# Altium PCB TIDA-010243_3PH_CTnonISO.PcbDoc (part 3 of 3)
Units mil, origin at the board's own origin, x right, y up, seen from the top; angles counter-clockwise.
Board outline 6131.89 x 7490.17 mil, 2 copper layers (Top Layer, Bottom Layer), stack 62 mil thick; 208 components, 218 nets, 747 pads, 147 vias.
Unrouted connection lines stored in the file: 258.
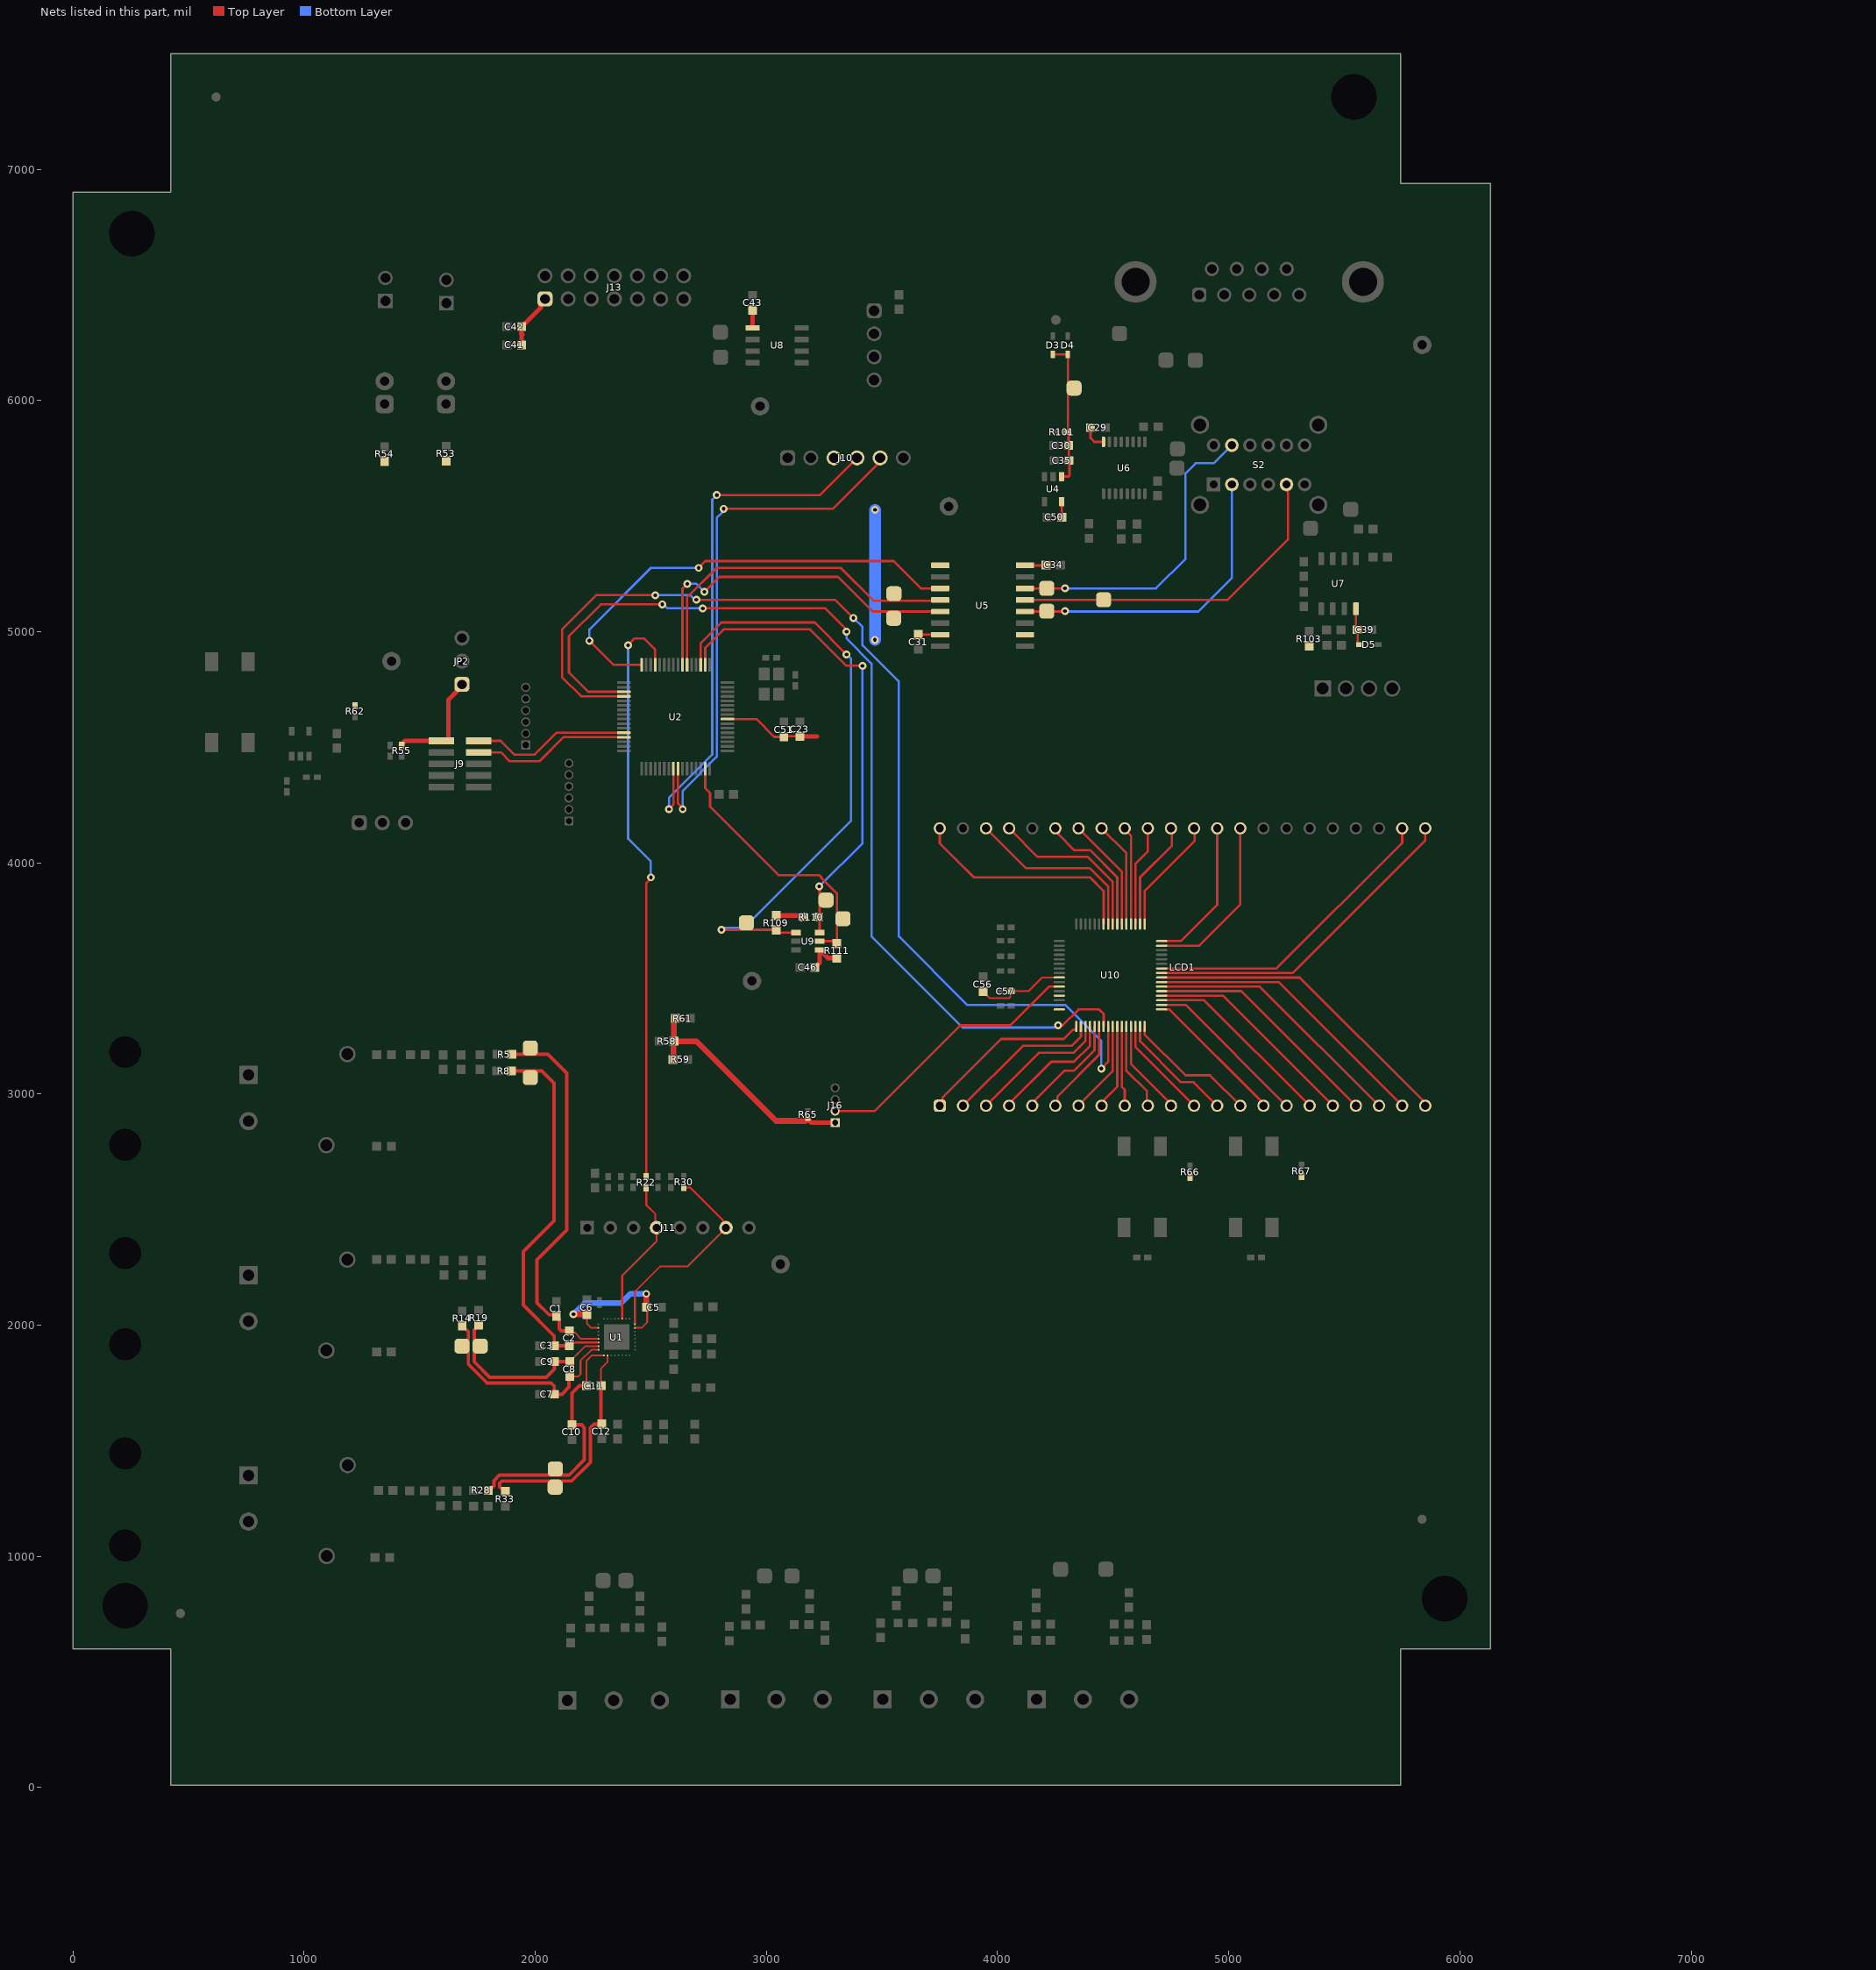
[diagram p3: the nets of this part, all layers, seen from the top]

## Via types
v1: diameter 34, hole 16, Top Layer to Bottom Layer, 97 vias
v2: diameter 34, hole 16, Top Layer to Bottom Layer, tented both sides, 41 vias
v3: diameter 23.62, hole 11.81, Top Layer to Bottom Layer, 9 vias

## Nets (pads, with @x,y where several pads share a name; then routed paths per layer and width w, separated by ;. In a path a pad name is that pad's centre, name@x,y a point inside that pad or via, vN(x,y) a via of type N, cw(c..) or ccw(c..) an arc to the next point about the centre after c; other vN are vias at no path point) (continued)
RXD_FTDI: J10.5 U2.25 | length 2333.1
  Top Layer w10: U2.25@2617.23,4407.26 2617.23,4256.97 2637.8,4236.4 v1(2637.8,4232.28) ; v2(2814.96,5531.5) 3287.4,5531.5 3476.02,5720.12 3476.02,5720.68 3491.88,5736.54 J10.5@3491.88,5751.41
  Bottom Layer w10: v1(2637.8,4232.28) 2637.8,4311.02 2785.43,4458.66 2785.43,5492.13 2807.25,5513.95 2807.25,5517.3 2814.96,5525 v2(2814.96,5531.5)
S0: LCD1.34 U10.50 | length 445.9
  Top Layer w10: U10.50@4616.14,3735.24 4616.14,3937.01 4753.94,4074.8 LCD1.34@4753.94,4124.02
S1: LCD1.33 U10.49 | length 502.2
  Top Layer w10: U10.49@4635.83,3735.24 4635.83,3877.95 4852.85,4094.97 4852.85,4134.34 LCD1.33@4862.2,4143.7
S2: LCD1.32 U10.48 | length 640.7
  Top Layer w10: U10.48@4709.65,3661.42 4793.31,3661.42 4950,3818.11 LCD1.32@4950,4149.21 ; LCD1.32@4950.79,4149.21 LCD1.32@4950.79,4153.54
S3: LCD1.31 U10.47 | length 743.6
  Top Layer w10: U10.47@4709.65,3641.73 4872.05,3641.73 5050,3819.68 LCD1.31@5050,4149.21
S4: LCD1.41 U10.56 | length 718.9
  Top Layer w10: LCD1.41@4055.12,4143.7 4055.51,4143.7 4173.43,4025.79 ; 4173.23,4025.59 4389.76,4025.59 4498.03,3917.32 U10.56@4498.03,3735.24
S5: LCD1.39 U10.55 | length 565.2
  Top Layer w10: LCD1.39@4250,4149.21 4250,4137.54 4262.7,4124.83 4262.7,4123.12 4330.71,4055.12 4399.61,4055.12 4517.72,3937.01 U10.55@4517.72,3735.24
S6: LCD1.38 U10.54 | length 491.6
  Top Layer w10: LCD1.38@4350,4149.21 4537.4,3961.81 U10.54@4537.4,3735.24
S7: LCD1.37 U10.53 | length 458.3
  Top Layer w10: LCD1.37@4450,4149.21 4557.09,4042.13 U10.53@4557.09,3735.24
S8: LCD1.36 U10.52 | length 422.5
  Top Layer w10: LCD1.36@4547.24,4143.7 4550.26,4143.7 4576.77,4117.19 U10.52@4576.77,3735.24
S9: LCD1.35 U10.51 | length 442.3
  Top Layer w10: U10.51@4596.46,3735.24 4596.46,3996.06 4650,4049.61 LCD1.35@4650,4149.21 LCD1.35@4645.67,4153.54
S10: LCD1.42 U10.57 | length 795
  Top Layer w10: LCD1.42@3950,4149.21 4122.84,3976.38 4399.61,3976.38 4478.35,3897.64 4478.35,3818.9 U10.57@4478.35,3735.24
S11: LCD1.44 U10.58 | length 996
  Top Layer w10: LCD1.44@3750,4143.7 3750,4084.65 3818.9,4015.75 3897.64,3937.01 4399.61,3937.01 4458.66,3877.95 U10.58@4458.66,3735.24
S12: LCD1.24 U10.42 | length 1328
  Top Layer w10: U10.42@4709.65,3543.31 5206.69,3543.31 5750,4086.61 LCD1.24@5750,4149.21
S13: LCD1.23 U10.41 | length 1429.5
  Top Layer w10: U10.41@4709.65,3523.62 5275.59,3523.62 5850,4098.03 LCD1.23@5850,4149.21
S14: LCD1.22 U10.40 | length 1376.8
  Top Layer w10: U10.40@4709.65,3503.94 5306.95,3503.94 5836.44,2974.45 LCD1.22@5858.13,2952.76
S15: LCD1.21 U10.39 | length 1272.5
  Top Layer w10: U10.39@4709.65,3484.25 4881.89,3484.25 5214.96,3484.25 LCD1.21@5750,2949.21 5756.3,2942.91 LCD1.21@5757.87,2942.91
S16: LCD1.8 U10.26 | length 371.2
  Top Layer w10: LCD1.8@4450,2949.21 4450,2960.89 4462.11,2973 4462.11,2975.89 4517.72,3031.5 U10.26@4517.72,3292.32
S17: LCD1.7 U10.25 | length 400.7
  Top Layer w10: LCD1.7@4350.39,2952.76 4498.03,3100.39 U10.25@4498.03,3292.32
S18: LCD1.6 U10.22 | length 421.4
  Top Layer w10: LCD1.6@4250,2949.21 4258.26,2957.47 4258.26,2988.57 4438.98,3169.29 U10.22@4438.98,3292.32
S19: LCD1.5 U10.21 | length 479.3
  Top Layer w10: LCD1.5@4150,2949.21 4150,2960.89 4163.1,2973.99 4163.1,2974.91 4288.58,3100.39 4330.71,3100.39 4419.29,3188.98 U10.21@4419.29,3292.32
S20: LCD1.4 U10.20 | length 545.6
  Top Layer w10: LCD1.4@4050,2949.21 4050,2957.48 4232.28,3139.76 4330.71,3139.76 4399.61,3208.66 U10.20@4399.61,3292.32
S21: LCD1.3 U10.19 | length 589.9
  Top Layer w10: LCD1.3@3950,2949.21 4179.92,3179.13 4330.71,3179.13 4379.92,3228.35 U10.19@4379.92,3272.72
S22: LCD1.2 U10.18 | length 658.7
  Top Layer w10: LCD1.2@3850,2949.21 4109.45,3208.66 4320.87,3208.66 4360.24,3248.03 U10.18@4360.24,3272.72
S23: LCD1.1 U10.17 | length 754.4
  Top Layer w10: LCD1.1@3750,2949.21 3761.68,2960.89 3761.68,2984.12 4015.75,3238.19 4286.42,3238.19 4326.57,3278.34 4340.47,3278.34 4340.55,3278.42 U10.17@4340.55,3292.32
S24: LCD1.20 U10.38 | length 1134.2
  Top Layer w10: U10.38@4729.25,3464.57 5134.65,3464.57 LCD1.20@5650,2949.21
S25: LCD1.19 U10.37 | length 1045.7
  Top Layer w10: U10.37@4709.65,3444.88 5054.33,3444.88 LCD1.19@5550,2949.21
S26: LCD1.18 U10.36 | length 937.5
  Top Layer w10: U10.36@4709.65,3425.2 4974.02,3425.2 LCD1.18@5450,2949.21
S27: LCD1.17 U10.35 | length 809.8
  Top Layer w10: U10.35@4729.25,3405.51 4893.7,3405.51 LCD1.17@5350,2949.21
S28: LCD1.16 U10.34 | length 716.2
  Top Layer w10: U10.34@4709.65,3385.83 4813.39,3385.83 LCD1.16@5246.46,2952.76
S29: LCD1.15 U10.33 | length 599.9
  Top Layer w10: U10.33@4729.25,3366.06 4744.17,3366.06 5150,2960.24 LCD1.15@5150,2949.21
S30: LCD1.14 U10.32 | length 588.1
  Top Layer w10: U10.32@4635.83,3292.32 4635.83,3257.87 4812.99,3080.71 4918.5,3080.71 LCD1.14@5050,2949.21 5056.3,2942.91 LCD1.14@5059.06,2942.91
S31: LCD1.13 U10.31 | length 522.6
  Top Layer w10: U10.31@4616.14,3292.32 4616.14,3228.35 4793.31,3051.18 4848.03,3051.18 4946.46,2952.76 LCD1.13@4960.63,2952.76
S32: LCD1.12 U10.30 | length 444.9
  Top Layer w10: U10.30@4596.46,3292.32 4596.46,3202.76 4836.61,2962.6 LCD1.12@4852.36,2962.6
S33: LCD1.11 U10.29 | length 399
  Top Layer w10: U10.29@4576.77,3292.32 4576.77,3129.92 LCD1.11@4744.09,2962.6
S34: LCD1.10 U10.28 | length 366.4
  Top Layer w10: U10.28@4557.09,3292.32 4557.09,3100.39 4645.67,3011.81 LCD1.10@4645.67,2962.6
S35: LCD1.9 U10.27 | length 343.7
  Top Layer w10: LCD1.9@4537.4,2962.6 4543.45,2962.6 4550,2969.15 4550,3018.9 4537.4,3031.5 U10.27@4537.4,3292.32
SCK_ADS_T: J11.4 R22.1 U1.19 | length 637.8
  Top Layer w8: 2375.74,2214.57 2445.39,2284.22 2524.8,2363.63 2524.8,2406.69 J11.4@2529.53,2411.42 ; U1.19@2375.98,2027.97 2375.98,2214.57 ; R22.1@2479.52,2594.49 2480.32,2593.69 2480.32,2519.69 2519.68,2480.32 2519.68,2431.1 J11.4@2527.17,2423.62
Serial_RE_DE: U2.64 U5.3 | length 2007.1
  Top Layer w10: v2(2234.25,4960.63) 2338.8,4856.08 U2.64@2459.75,4856.08 ; v1(2706.69,5275.59) 2736.22,5305.12 3550.22,5305.12 3668.44,5186.9 U5.3@3752.07,5186.9
  Bottom Layer w10: v2(2234.25,4960.63) 2234.25,5009.84 2500,5275.59 v1(2706.69,5275.59)
Serial_RE_DE_ISO: pad.2@4212.6,5187.01 S2.11 U5.14 | length 1368.3
  Top Layer w10: U5.14@4118.21,5186.9 4291.23,5186.9 v1(4291.34,5187.01)
  Bottom Layer w10: v1(4291.34,5187.01) 4685.31,5187.01 4812.99,5314.69 4812.99,5684.8 4856.4,5728.21 4935.5,5728.21 S2.11@5013.26,5805.97
Serial_RX: pad.2@3550.51,5057.79 U2.55 U5.5 | length 1565.2
  Top Layer w10: U2.55@2636.91,4856.08 2636.91,5186.12 v2(2657.48,5206.69) ; v2@2726.38,5177.17 v2(2731.7,5171.84) 2731.7,5172.65 2795.95,5236.9 3309.82,5236.9 3459.82,5086.9 U5.5@3752.07,5086.9
  Bottom Layer w10: v2(2657.48,5206.69) 2696.85,5206.69 v2(2731.7,5171.84)
Serial_RX_ISO: pad.1@4212.6,5088.58 S2.2 U5.12 | length 1361.3
  Top Layer w10: U5.12@4118.21,5086.9 4289.65,5086.9 v1(4291.34,5088.58)
  Bottom Layer w10: v1(4291.34,5088.58) 4293.02,5086.9 4868.37,5086.9 5013.26,5231.78 S2.2@5013.26,5636.67
Serial_TX: pad.1@3551.63,5164.02 U2.54 U5.4 | length 1499.6
  Top Layer w10: U2.54@2656.6,4856.08 2656.6,5146.75 2785.43,5275.59 3321.13,5275.59 3462.98,5133.74 3748.92,5133.74 U5.4@3752.07,5136.9
Serial_TX_ISO: pad.3@4458.66,5137.8 S2.5 U5.13 | length 1487.1
  Top Layer w10: U5.13@4118.21,5136.9 4993.55,5136.9 5256.69,5400.04 5256.69,5629.46 S2.5@5249.48,5636.67
SMCLK: U10.16
SPI_SCK: R22.2 U2.61 | length 2565
  Top Layer w10: v2(2401.57,4940.94) 2401.57,4942.62 2429.43,4970.47 2470.47,4970.47 2518.8,4922.14 U2.61@2518.8,4856.08 ; R22.2@2479.52,2641.73 2479.92,2642.13 2479.92,3911.84 2500,3931.92 v1(2500,3937.01)
  Bottom Layer w10: v2(2401.57,4940.94) 2401.57,4104.33 2500,4005.91 v1(2500,3937.01)
SWCLK: J9.4 U2.13 | length 687.4
  Top Layer w10: J9.4@1754.72,4477.56 1851.18,4477.56 1889.76,4438.98 2017.72,4438.98 2121.83,4543.09 U2.13@2382.97,4543.09
SWDIO: J9.2 U2.12 | length 674.8
  Top Layer w10: J9.2@1771.65,4527.56 1850.39,4527.56 1909.45,4468.5 1998.03,4468.5 2092.3,4562.77 2336.84,4562.77 U2.12@2382.97,4562.77
SYNC_RESET_ADS_T: J11.7 R30.1 U1.16 | length 915.2
  Top Layer w8: U1.16@2431.1,2003.94 2431.1,2145.67 2539.37,2253.94 2657.48,2253.94 J11.7@2824.8,2421.26 2815.03,2431.03 2815.03,2450.71 2670.13,2595.61 R30.1@2642.94,2595.61
TEST/SBWTCK: J16.2 U10.11 | length 1166.9
  Top Layer w10: J16.2@3307.09,2921.8 3307.09,2922.6 3310.81,2926.32 3467.66,2926.32 3838.58,3297.24 4055.12,3297.24 4222.44,3464.57 U10.11@4247.13,3464.57 ; J16.2@3307.09,2930.05 J16.2@3307.09,2931.64
TMAG_INT: pad.1@3331.38,3758.29 R111.1 U2.31 U9.5 | length 1172.8
  Top Layer w10: U2.31@2735.34,4407.26 2735.34,4323.06 2756.25,4302.14 2756.25,4242.47 3051.87,3946.85 3228.35,3946.85 3238.19,3937.01 ; U9.5@3230.31,3660.89 3295.33,3660.89 R111.1@3304.83,3651.39 3304.83,3867.66 3236.84,3935.66
TMAG_SCL: pad.1@2913.39,3740.16 R109.1 U2.51 U9.1 | length 2628.6
  Top Layer w10: U2.51@2715.65,4856.08 2715.65,4949.9 2805.12,5039.37 3208.66,5039.37 v2(3346.46,4901.57) ; v1(2805.12,3710.63) R109.1@3041.34,3710.63 ; R109.1@3042.19,3709.05 3052.96,3698.29 U9.1@3127.95,3698.29
  Bottom Layer w10: v1(2805.12,3710.63) 2811.61,3710.63 2819.32,3718.34 2901.41,3718.34 3366.14,4183.07 3366.14,4881.89 v2(3346.46,4901.57)
TMAG_SDA: pad.1@3257.87,3838.58 R110.1 U2.50 U9.6 | length 2084.7
  Top Layer w10: U2.50@2735.34,4856.08 2735.34,4930.22 2814.96,5009.84 3188.98,5009.84 3346.46,4852.36 v2(3415.35,4852.36) ; v1(3228.35,3897.64) 3230.31,3895.67 U9.6@3230.31,3698.29
  Bottom Layer w10: v1(3228.35,3897.64) 3415.35,4084.65 v2(3415.35,4852.36)
TPS709_IN: C30.1 C35.1 D3.1 D4.1 pad.1@4330.71,6053.15 R101.1 U4.1 | length 629.9
  Top Layer w10: D3.1@4239.31,6199.54 D4.1@4303.79,6199.54 ; U4.1@4277.29,5670.7 4306.93,5670.7 4310.76,5674.53 4310.76,5737.98 C35.1@4308.71,5740.02 4308.71,5803.81 C30.1@4307.39,5805.13 4307.39,5856.19 R101.1@4300.96,5862.63 4303.79,5865.47 4303.79,5893.5 D4.1@4303.79,6199.54 ; D4.1@4303.9,6199.44 D4.1@4303.79,6199.54
TXD_FTDI: J10.4 U2.24 | length 2289.9
  Top Layer w10: v1(2578.74,4232.28) 2578.74,4232.6 2597.54,4251.4 U2.24@2597.54,4407.26 ; v2@2795.28,5590.55 2795.62,5590.9 3231.37,5590.9 J10.4@3391.88,5751.41
  Bottom Layer w10: v1(2578.74,4232.28) 2578.74,4281.5 2765.75,4468.5 2765.75,5570.87 v2(2785.43,5590.55)
UART2_RX_M0: U2.4 U10.24 | length 4697.5
  Top Layer w10: U2.4@2382.97,4720.25 2199.04,4720.25 2116.14,4803.15 2116.14,5009.84 2263.78,5157.48 v2(2519.68,5157.48) ; v2(2696.85,5137.8) 3297.24,5137.8 v2(3375.98,5059.06) ; v2(4448.82,3110.24) 4478.35,3139.76 U10.24@4478.35,3292.32
  Bottom Layer w10: v2(2519.68,5157.48) 2671.28,5157.48 2687.01,5141.75 v2@2687.01,5137.8 ; v2(3375.98,5059.06) 3415.35,5019.69 3415.35,4940.94 3572.83,4783.46 3572.83,3681.1 3868.11,3385.83 4291.34,3385.83 4448.82,3228.35 v2(4448.82,3110.24)
UART2_TX_M0: U2.3 U10.23 | length 4367.3
  Top Layer w10: U2.3@2382.97,4739.94 2228.57,4739.94 2145.67,4822.83 2145.67,4980.31 2283.46,5118.11 v2(2549.21,5118.11) ; v2(2724.8,5100.59) 3255.71,5100.59 v2@3346.46,5009.84 ; v2(4261.81,3297.24) 4281.5,3297.24 4350.39,3366.14 4438.98,3366.14 4458.66,3346.46 U10.23@4458.66,3292.32
  Bottom Layer w10: v2(2549.21,5118.11) 2555.71,5118.11 2573.23,5100.59 v2(2724.8,5100.59) ; v2@3346.46,5009.84 3346.46,4970.47 3454.72,4862.2 3454.72,3681.1 3848.43,3287.4 4245.47,3287.4 4255.32,3297.24 v2(4261.81,3297.24)
  other v2: 3346.46,5000
V_Phase_A_N: C2.2 C3.2 pad.1@1978.35,3070.87 R8.2 U1.30 | length 1648.2
  Top Layer w6: C2.2@2147.74,1912.43 C2.2@2160.51,1925.2
  Top Layer w8: C2.2@2160.51,1925.2 U1.30@2273.62,1925.2
  Top Layer w15: R8.2@1896.51,3099.32 2028.63,3099.32 2080.68,3047.27 2080.68,2450.68 1948.82,2318.82 1948.82,2086.61 2082.19,1953.24 C3.2@2082.19,1911.7 2147.01,1911.7 C2.2@2147.74,1912.43
V_Phase_A_P: C1.1 C2.1 pad.2@1978.35,3198.82 R5.2 U1.29 | length 1674.4
  Top Layer w6: C2.1@2147.74,1975.42 2147.74,1974.44 C2.1@2153.85,1968.33
  Top Layer w8: C2.1@2153.85,1968.33 2171.07,1968.33 2198.45,1940.94 U1.29@2273.62,1940.94
  Top Layer w15: R5.2@1898.47,3171.41 1978.35,3171.41 2054.97,3171.41 2135.83,3090.55 2135.83,2411.42 2007.87,2283.46 2007.87,2096.46 2059.36,2044.97 2086.4,2044.97 C1.1@2091.78,2039.59 2091.78,2038.61 2103.31,2027.08 2103.31,1984.21 2112.09,1975.42 C2.1@2147.74,1975.42
V_Phase_B_N: C8.2 C9.2 pad.4@1761.81,1909.45 R19.2 U1.31 | length 807.5
  Top Layer w6: C8.2@2148.66,1842.22 C8.2@2149.28,1841.6
  Top Layer w8: C8.2@2148.91,1842.22 2182.52,1875.83 2216.14,1909.45 U1.31@2273.62,1909.45
  Top Layer w15: R19.2@1755.17,2000.57 1755.17,1999.59 1735.53,1979.95 1735.53,1909.45 1735.53,1841.81 1802.37,1774.97 2046.48,1774.97 2082.51,1811 C9.2@2082.51,1842.22 2148.66,1842.22 C8.2@2148.91,1842.22
V_Phase_B_P: C7.1 C8.1 pad.3@1683.07,1909.45 R14.2 U1.32 | length 955.4
  Top Layer w8: C8.1@2149.28,1778.61 2186.17,1778.61 2196.02,1788.45 2196.02,1846.89 2242.83,1893.7 U1.32@2273.62,1893.7
  Top Layer w15: R14.2@1684.11,1997.85 1710.53,1971.43 1710.53,1909.45 1710.53,1831.45 1792.01,1749.97 2068.93,1749.97 2082.19,1736.7 C7.1@2082.19,1701.33 2114.72,1701.33 2145.67,1732.28 C8.1@2145.67,1781.5
V_Phase_C_N: C11.2 C12.2 pad.2@2086.05,1299.52 R33.2 U1.2 | length 995.8
  Top Layer w6: U1.2@2312.99,1868.1 2312.21,1868.88 U1.2@2312.99,1869.67
  Top Layer w8: C12.2@2284.57,1574.88 C12.2@2287.45,1572 ; C11.2@2284.57,1738.24 2284.57,1812.82 2312.21,1840.45 ; 2313.09,1840.78 U1.2@2313.09,1869.21
  Top Layer w15: R33.2@1870.12,1280.2 1870.12,1281.18 1858.92,1292.38 1854.82,1292.38 1846.03,1301.17 1846.03,1317.38 1854.82,1326.17 2086.05,1326.17 2156.98,1326.17 2230.45,1399.65 2237.78,1406.97 2237.78,1556.5 2253.27,1572 C12.2@2287.45,1572 ; C12.2@2284.57,1574.88 C11.2@2284.57,1738.24
V_Phase_C_P: C10.1 C11.1 pad.1@2086.61,1377.95 R28.2 U1.1 | length 1089.3
  Top Layer w6: U1.1@2296.22,1868.88 2297,1869.67 U1.1@2297.24,1869.67
  Top Layer w8: C11.1@2220.6,1738.24 C11.1@2221.58,1738.24 2221.58,1846.21 2245.03,1869.67 U1.1@2297,1869.67
  Top Layer w15: R28.2@1796.95,1285.54 1808.15,1296.74 1812.24,1296.74 1821.03,1305.53 1821.03,1327.74 1844.46,1351.17 2086.61,1351.17 2146.62,1351.17 2212.78,1417.32 2212.78,1556.5 2199.98,1569.3 C10.1@2158.73,1569.3 2158.73,1705.98 2191,1738.24 C11.1@2220.6,1738.24
VCC_EXTERN: C5.1 C6.1 C23.2 C31.1 C41.1 C42.2 C43.1 C46.1 C51.1 C56.1 C57.1 J9.1 J10.3 J13.1 J16.1 JP2.1 R53.2 R54.2 R55.2 R58.1 R59.2 R61.2 R62.1 R65.2 R66.2 R67.2 R109.2 R110.2 R111.2 U1.15 U1.26 U2.40 U5.1 U5.7 U8.1 U9.4 U10.9 | length 4277.9
  Top Layer w6: U5.7@3750.74,4988.23 U5.7@3752.07,4986.9
  Top Layer w8: C6.1@2222.82,2046.27 2222.82,2007.86 2227.51,2003.17 2242.49,1988.19 U1.26@2273.21,1988.19 ; U1.15@2431.1,1988.19 2459.15,1988.19 2483.99,2013.03 2483.99,2075.22 C5.1@2481.45,2077.77 ; C56.1@3937.01,3442.91 3937.01,3441.93 3951.71,3427.23 3952.69,3427.23 3964.57,3415.35 4050.43,3415.35 4055.12,3420.04 4055.12,3444.88 4133.86,3444.88 4192.91,3503.94 U10.9@4266.73,3503.94
  Top Layer w10: U2.40@2831.79,4621.83 2956.92,4621.83 3033.87,4544.87 C51.1@3075.57,4544.87 3077.94,4547.24 C23.2@3149.61,4547.24 ; C23.2@3143.49,4544.87 3144.88,4546.26 C23.2@3144.88,4546.36 ; C31.1@3657.22,4986.9 3750.74,4986.9 U5.7@3751.41,4987.56
  Top Layer w20: R55.2@1417.32,4507.87 1437.01,4527.56 J9.1@1594.49,4527.56 1619.45,4527.56 1624.02,4532.13 1624.02,4704.72 1664.44,4745.15 1664.44,4750.04 1678.18,4763.78 JP2.1@1683.07,4763.78 ; 1938.98,6289.37 1940.94,6287.4 ; C41.1@1939.4,6250.56 1940.94,6252.11 1940.94,6287.4 ; 1940.94,6289.37 C42.2@1940.94,6318.9 1941.93,6318.9 2023.6,6400.57 2023.6,6423.21 J13.1@2037.4,6437.01 ; 1943.8,6284.54 1940.94,6287.4 ; U8.1@2940.24,6313.18 C43.1@2940.24,6391.11 ; R109.2@3042.19,3772.05 3137.4,3772.05 R110.2@3149.61,3759.84 ; C23.2@3144.88,4546.36 3217.62,4546.36 ; R65.2@3181.13,2889.45 3194.26,2876.32 J16.1@3297.24,2876.32 ; C46.1@3209.29,3547.71 3230.31,3568.73 U9.4@3230.31,3623.48 3265.41,3588.39 R111.2@3304.83,3588.39 R111.2@3305.44,3587.79
  Top Layer w25: v1(2165.35,2047.24) 2221.85,2047.24 C6.1@2222.82,2046.27 ; C5.1@2480.32,2076.77 v1(2480.32,2135.83) ; R59.2@2598.43,3149.61 2598.43,3226.38 R58.1@2600.39,3228.35 ; R61.2@2600.39,3334.65 R58.1@2600.39,3228.35 ; R65.2@3179.13,2893.7 3169.29,2883.86 3041.34,2883.86 2696.85,3228.35 R58.1@2600.39,3228.35
  Bottom Layer w25: v1(2165.35,2047.24) 2214.57,2096.46 2372.05,2096.46 2411.42,2135.83 v1(2480.32,2135.83)
  Bottom Layer w50: v1(3469.62,4964.42) 3470.03,4964.83 v1(3470.03,5526.96)
VCC_ISO_RS: C29.2 C34.1 C39.1 C50.1 D5.1 R103.2 U4.5 U5.10 U5.16 U6.16 U7.8 | length 432.8
  Top Layer w10: U5.16@4118.21,5286.9 4145.77,5286.9 4146.56,5286.11 4206.72,5286.11 4208.69,5288.08 C34.1@4209.67,5288.08 ; C50.1@4277.22,5495.02 4277.22,5562.36 U4.5@4277.29,5562.43 ; C29.2@4401.88,5882.58 4401.88,5837.03 4418.18,5820.73 U6.16@4458.31,5820.73 ; U7.8@5549.99,5098.43 5549.99,5013.87 C39.1@5555.8,5008.07 5557.17,5006.69 5557.17,4948.87 5562.02,4944.03 D5.1@5566.62,4944.03
WAKE_IN: U10.13
pads on no net: FID1.1 FID2.1 FID3.1 H13. H14. H15. H16. H_IA1. H_IA2. H_IB1. H_IB2. H_IC1. H_IC2. J9.6 J9.8 J11.8 J13.8 J13.10 J13.11 J13.12 LBL1.0 LCD1.29 LCD1.30 LCD1.40 LCD1.43 RS1.1 RS1.6 RS1.8 RS1.9 S1.2 S1.4 S2.7 S2.8 S2.9 S2.12 S2.MH1 S2.MH2 S2.MH3 S2.MH4 U1.11 U1.12 U1.14 U1.22 U1.27 U4.4 U5.6 U5.11 U6.7 U6.8 U6.9 U10.6 U10.61 U10.62 U10.63 U10.64

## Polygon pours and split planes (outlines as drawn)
GND on Top Layer "TOP_LAYER_GND_P024" (solid, remove dead copper, pour order 24): 492.13,6837.06 492.13,1973.83 492.13,108.27 5708.66,108.27 5708.66,698.82 6103.15,698.82 6103.15,4377.6 3828.74,4377.6 3828.74,6837.06
VCC_ISO_RS on Top Layer "TOP_LAYER_VCC_ISO_RS_P019" (solid, remove dead copper, pour order 19): 4039.07,4596.46 4039.07,5374.01 4039.07,6830.71 6043.89,6830.71 6043.89,4596.46
DVDD_ISO_Pulse on Top Layer "TOP_LAYER_DVDD_ISO_PULSE_P020" (solid, remove dead copper, pour order 20): 3048.51,6618.15 3050.12,5928.41 3647.96,5928.41 3652.86,5928.41 3652.87,6618.15 3049.86,6618.15
VCC_EXTERN on Top Layer "TOP_LAYER_VCC_EXTERN_P022" (solid, remove dead copper, pour order 22): 1043.31,6837.06 2542.23,6837.06 3825.92,6837.06 3825.92,4379.98 6102.36,4379.86 6102.36,2194.88 2627.31,2194.88 2627.31,1914.23 2293.31,1914.23 2293.31,4330.71 1028.96,4330.71
GND_ISO_RS on Bottom Layer "BOTTOM_LAYER_GND_ISO_RS_P018" (solid, remove dead copper, pour order 18): 4039.07,4596.46 4039.07,6837.06 6043.89,6837.06 6043.89,4596.46
GND_ISO_Pulse on Bottom Layer "BOTTOM_LAYER_GND_ISO_PULSE_P021" (solid, remove dead copper, pour order 21): 3652.82,6028.75 3105.6,6028.71 3105.6,6578.52 3652.82,6578.49
GND on Bottom Layer "BOTTOM_LAYER_GND_P026" (solid, remove dead copper, pour order 26): 492.13,6837.06 3828.74,6837.06 3825.92,6834.23 3825.92,4379.98 6102.24,4379.98 6102.36,4379.86 6102.36,698.82 5708.66,698.82 5708.66,108.27 492.13,108.27

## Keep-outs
Top Layer:
  region: 3070.87,4488.19 2942.91,4616.14 2893.7,4616.14 2903.54,4625.98 2903.54,4862.2 3031.5,4990.16 3198.82,4990.16 3198.82,4488.19
Keep-Out Layer:
  text ".Layer_Name" at 577,-848.65 h60

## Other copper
Top Layer:
  pour cut-out: 2792.47,4627.72 2792.47,4616.15 2801.98,4616.15 2802.23,4616.39 2802.15,4616.48 2802.15,4627.64 2792.55,4627.64
  text ".Layer_Name" at 577,-848.65 h60
Bottom Layer:
  text ".Layer_Name" at 577,-848.65 h60

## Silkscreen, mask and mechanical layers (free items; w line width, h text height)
Top Overlay:
  lines w10: 1505.91,4370.08 1476.38,4370.08 1476.38,4478.35 ; 1505.91,4478.35 1476.38,4478.35 ; 3051.18,5541.34 3011.81,5541.34 3011.81,5629.92 ; 3051.18,5895.67 3011.81,5895.67 3011.81,5856.3 3011.81,5629.92 ; 3523.62,5541.34 3671.26,5541.34 3671.26,5895.67 3631.89,5895.67 ; 6745.2,-560.75 6745.2,44.25 7635.2,44.25 7635.2,-5.75 7635.2,-560.75 7340.2,-560.75 7045.2,-560.75 6750.2,-560.75 ; 1476.38,4478.35 1476.38,4478.35 ; 3011.81,5629.92 3011.81,5629.92 ; 1476.38,4724.41 1574.8,4724.41 1771.65,4724.41 1840.55,4724.41 1840.55,5019.68 1771.65,5019.68 1574.8,5019.68 1476.38,5019.68 1476.38,4724.41 ; 5187.01,5984.25 5433.07,5984.25 5433.07,6072.83 5187.01,6072.83 5187.01,6062.99 5187.01,5984.25 ; 5324.8,5994.09 5413.39,5994.09 5413.39,6062.99 5324.8,6062.99 5324.8,5994.09
  text "TIDA-010243.Rev2" at 3141.05,7256.61 h108.27
  text "RX_UART" at 2046.09,6620.17 h30 r90
  text "TX_UART" at 2154.36,6620.17 h30 r90
  text "GPIO_UART" at 2252.78,6620.17 h30 r90
  text "ISO-RS232" at 3976.54,6535.59 h50
  text "GND" at 2712.69,6531.59 h30
  text "REACT" at 1118.2,6403.64 h30
  text "ACT" at 1708.76,6403.64 h30
  text "GND" at 2653.64,6344.58 h30
  text "M0_EN" at 2279.62,6320.05 h30
  text "ACT" at 2159.35,6275.68 h30 r90
  text "REACT" at 2247.94,6216.63 h30 r90
  text "GPIO1" at 2454.63,6128.05 h30 r90
  text "GND_ISO_RS" at 5714.66,6113.36 h30
  text "VCC_EXTERN" at 2055.93,6059.15 h30 r90
  text "SW_RS232" at 4851.52,6009.76 h40
  text "SW_RS485" at 5481.44,6009.76 h40
  text "GND" at 2811.12,5980.41 h30
  text "FTDI_UART_USB" at 3165.45,5906.67 h30
  text "6pin nonISO" at 3175.29,5852.61 h30
  text "BLACK" at 3104.24,5832.77 h30 r90
  text "GREEN" at 3606.2,5832.77 h30 r90
  text "VCC_EXT" at 3278.71,5663.29 h30 r270
  text "GND" at 3756,5626.08 h30
  text "TXD" at 3409.35,5586.71 h30 r90
  text "RXD" at 3507.78,5586.71 h30 r90
  text "CTS" at 3212.5,5567.02 h30 r90
  text "RTS" at 3606.2,5567.02 h30 r90
  text "GND" at 3114.08,5537.5 h30 r90
  text "BSL_MSPM0G" at 1427.32,5077.39 h50
  text "RESET_MSPM0G" at 520.81,4976.29 h40
  text "GND" at 1531.59,4956.79 h30
  text "BSL" at 1511.91,4858.36 h30
  text "VCC" at 1531.59,4759.94 h30
  text "ISO_RS485" at 4763.94,4703.37 h50
  text "RS485_A" at 5422.07,4366.24 h30 r90
  text "RS485_B" at 5520.5,4366.24 h30 r90
  text "RS485_VCC" at 5628.77,4297.34 h30 r90
  text "RS485_GND" at 5717.35,4297.34 h30 r90
  text "JTAG_M0G" at 1565.12,4191.56 h50
  text "GND" at 3391.83,3017.81 h30
  text "TDIO" at 3391.83,2958.76 h30
  text "TCK" at 3391.83,2899.7 h30
  text "VCC" at 3391.83,2840.65 h30
  text "JTAG_430" at 3238.35,2733.2 h40
  text "SYNC" at 2845.33,2528.69 h40 r90
  text "ADS131M08 Interface" at 3090.71,2401.73 h40
  text "CLK" at 2244.94,2233.41 h40 r90
  text "DIN" at 2333.52,2233.41 h40 r90
  text "/CS" at 2746.91,2233.41 h40 r90
  text "GND" at 2943.76,2233.41 h40 r90
  text "DOUT" at 2451.63,2203.88 h40 r90
  text "DRDY" at 2648.48,2203.88 h40 r90
  text "SCLK" at 2550.06,2194.04 h40 r90
  text ".Layer_Name" at 577,-848.65 h60
Bottom Overlay:
  text ".Layer_Name" at 577,-848.65 h60
Top Paste:
  text ".Layer_Name" at 577,-848.65 h60
Bottom Paste:
  text ".Layer_Name" at 577,-848.65 h60
Top Solder:
  text ".Layer_Name" at 577,-848.65 h60
  text ".Layer_Name" at 577,-848.65 h60
Bottom Solder:
  text ".Layer_Name" at 577,-848.65 h60
Drill Guide:
  text ".Layer_Name" at 577,-848.65 h60
M1 Board Outline:
  lines w10: 422.65,7490.16 424.3,7491.81 ; 5735.96,7491.81 5737.61,7490.16 ; 6130.95,6928.77 6131.31,6929.13
  lines w47.24: 6135.97,600.39 cw(c6130.95,600.39) 6130.95,595.38 5742.63,595.38 5742.63,9.84 cw(c5737.61,9.84) 5737.61,4.83 422.65,4.83 cw(c422.65,9.84) 417.64,9.84 417.64,595.38 28.95,595.38 cw(c28.95,600.39) 23.94,600.39 23.94,6899.61 cw(c28.95,6899.61) 28.95,6904.62 417.64,6904.62 417.64,7490.16 cw(c422.65,7490.16) 419.12,7493.72 420.76,7495.35 cw(c424.29,7491.84) 424.3,7496.82 5735.96,7496.82 cw(c5735.96,7491.81) 5739.52,7495.34 5741.16,7493.7 cw(c5737.64,7490.17) 5742.63,7490.16 5742.63,6934.15 6131.31,6934.15 cw(c6131.31,6929.13) 6136.33,6929.13 6136.33,604.2
  text ".Layer_Name" at 577,-848.65 h60
M2 Board Dimensions:
  rectangle: 0,-265.16 125,-140.16
  rectangle: 125,-390.16 500,-265.16
  lines w7: 0,-265.16 1000,-265.16 ; 125,-390.16 125,-140.16 ; 250,-390.16 250,-140.16 ; 500,-390.16 500,-140.16 ; 750,-390.16 750,-140.16 ; 0,-390.16 1000,-390.16 1000,-140.16 0,-140.16 0,-390.16
  text ".Layer_Name" at 577,-848.65 h60
M3 3D STEP Top:
  text ".Layer_Name" at 577,-848.65 h60
M4 3D STEP Bottom:
  text ".Layer_Name" at 577,-848.65 h60
M5 Assembly Top:
  lines w10: -292,-920.32 6308,-920.32 ; -292,-716.99 6310,-716.99 ; -292,-513.66 -292,-1123.66 3713,-1123.66 6310,-1123.66 6310,-513.66 -291.5,-513.66 -291.5,-1123.66 1284,-1123.66 ; 2173,-1123.66 2173,-513.66 ; 3440,-716.99 3440,-513.66 ; 4280,-716.99 4280,-513.66 ; 4902,-1130.16 4902,-927.32
  text "COMPONENTS MARKED 'DNP' SHOULD NOT BE POPULATED." at 1153.5,-308.66 h60
  text "ASSEMBLY VARIANT:" at 1153,-424.16 h60
  text ".VariantName" at 2189,-424.16 h60
  text "PCB VIEWED FROM TOP SIDE" at -228.5,-645.82 h60
  text "BOARD #:" at 2248,-645.82 h60
  text ".PRJ_Number" at 2793.5,-645.82 h60
  text "REV:" at 3638,-645.82 h60
  text ".PCB_Rev" at 3929.5,-645.82 h60
  text "SVN REV:" at 4476,-645.82 h60
  text ".VersionControl_RevNumber" at 4982,-645.82 h60
  text "TID #:" at 2248,-849.16 h60
  text ".TID" at 2793.5,-849.16 h60
  text "PLOT NAME =" at -228.5,-1054.49 h60
  text ".plot_File_Name" at 577,-1054.49 h60
  text "GENERATED    :" at 2250,-1054.49 h60
  text ".Print_Date" at 3119.5,-1054.49 h60
  text ".Print_Time" at 3848.5,-1054.49 h60
  text "TEXAS INSTRUMENTS" at 5113,-1054.49 h60
M6 Assembly Bottom:
  lines w10: -292.5,-717.49 6309.5,-717.49 ; -290.5,-920.82 6309.5,-920.82 ; 1115.5,-1130.66 1115.5,-927.82 ; 1737.5,-717.49 1737.5,-514.16 ; 2577.5,-717.49 2577.5,-514.16 ; 3844.5,-1124.16 3844.5,-514.16 ; 4733.5,-1124.16 6309,-1124.16 6309,-514.16 -292.5,-514.16 -292.5,-1124.16 2304.5,-1124.16 6309.5,-1124.16 6309.5,-514.16
  text "COMPONENTS MARKED 'DNP' SHOULD NOT BE POPULATED." at 6102,-308.16 h60
  text ".VariantName" at 5058,-424.16 h60
  text "ASSEMBLY VARIANT:" at 6097,-424.16 h60
  text ".VersionControl_RevNumber" at 1035.5,-646.32 h60
  text "SVN REV:" at 1541.5,-646.32 h60
  text ".PCB_Rev" at 2088,-646.32 h60
  text "REV:" at 2379.5,-646.32 h60
  text ".PRJ_Number" at 3224,-646.32 h60
  text "BOARD #:" at 3769.5,-646.32 h60
  text "PCB VIEWED FROM BOTTOM SIDE" at 6246,-646.32 h60
  text ".TID" at 3224,-849.66 h60
  text "TID #:" at 3769.5,-849.66 h60
  text "TEXAS INSTRUMENTS" at 904.5,-1054.99 h60
  text ".Print_Time" at 2169,-1054.99 h60
  text ".Print_Date" at 2898,-1054.99 h60
  text "GENERATED    :" at 3767.5,-1054.99 h60
  text ".plot_File_Name" at 5440.5,-1054.99 h60
  text "PLOT NAME =" at 6246,-1054.99 h60
M9 Title Sheet:
  drawing of 57 lines, arcs and shapes, not listed
  text "1" at 739.84,8046.34 h70
  text "2" at 3235.5,8046.34 h70
  text "3" at 5724.84,8046.34 h70
  text "4" at 8231.51,8046.34 h70
  text "5" at 10730.5,8046.34 h70
  text "6" at 13235.5,8046.34 h70
  text "A" at -416.5,6903.34 h70
  text "A" at 14383.5,6903.34 h70
  text "B" at -416.5,4523.34 h70
  text "B" at 14383.5,4523.34 h70
  text "C" at -416.5,2148.34 h70
  text "C" at 14383.5,2148.34 h70
  text "PROJECT TITLE:" at 11343.5,287.34 h45
  text ".PRJ_Title" at 11393.5,154.02 h70
  text "DESIGNED FOR:" at 11343.5,-13.66 h45
  text ".PRJ_Customer" at 11393.5,-153.66 h70
  text "D" at -416.5,-221.66 h70
  text "D" at 14383.5,-221.66 h70
  text "FILE NAME:" at 11343.5,-313.66 h45
  text ".PCB_File_Name_No_Path" at 11393.5,-433.66 h70
  text "Texas Instruments (TI) and/or its licensors do not warrant the accuracy or completeness of this specification" at 6374,-595.5 h45
  text "ENGINEER:" at 11343.5,-603.66 h45
  text "LAYOUT BY:" at 12848.5,-603.66 h45
  text "or any information contained therein. TI and/or its licensors do not warrant that this design will meet" at 6329.01,-708.16 h45
  text ".PRJ_Engineer" at 11393.5,-758.65 h70
  text ".PCB_Layout" at 12899,-758.65 h70
  text "the specifications, will be suitable for your application or fit for any particular purpose, or will operate in" at 6329.01,-820.83 h45
  text ".Layer_Name" at 577,-848.65 h60
  text "ALTIUM DESIGNER VERSION:" at 12848.5,-913.66 h45
  text "an implementation. TI and/or its licensors do not warrant that the design is production worthy. You should" at 6329.01,-933.49 h45
  text "completely validate and test your design implementation to confirm the system functionality for your application." at 6374,-1046.16 h45
  text ".print_Scale" at 11393.5,-1046.98 h70
  text ".Application_BuildNumber" at 12899,-1046.98 h70
  text "1" at 739.84,-1253.66 h70
  text "2" at 3235.5,-1253.66 h70
  text "3" at 5724.84,-1253.66 h70
  text "4" at 8231.51,-1253.66 h70
  text "5" at 10730.5,-1253.66 h70
  text "6" at 13235.5,-1253.66 h70
M10 Fab Notes:
  drawing of 189 lines, arcs and shapes, not listed
  text "DESIGN INFORMATION" at 12382.02,6366.02 h60
  text "MIN. TRACK WIDTH:" at 11737.46,6233.89 h60
  text "8" at 12833.7,6233.89 h60
  text "MIL" at 12988.46,6233.89 h60
  text "7.874" at 12667.32,6112.2 h60
  text "MIN. CLEARANCE:" at 11737.46,6109.76 h60
  text "MIL" at 12988.46,6109.76 h60
  text "MIN. VIA PAD SIZE:" at 11737.46,5985.64 h60
  text "24" at 12803.71,5985.64 h60
  text "MIL" at 12988.46,5985.64 h60
  text "0.05mm (2MIL)" at 12432.46,5855.74 h60
  text "MINIMUM ANNULAR RING" at 11408.23,5847.52 h60
  text "EXTERNAL" at 13140.46,5847.52 h60
  text "PER" at 11608.23,5737.39 h60
  text "IPC-D-275 CLASS 2 LEVEL C" at 11828.23,5737.39 h60
  text "MIL, HOLES" at 13316.46,5636.91 h60
  text "+/-" at 12924,5628.33 h60
  text "+/-" at 13778,5628.33 h60
  text "REGISTRATION TOLERANCES:" at 11408.23,5627.26 h60
  text "METAL" at 12608,5627.26 h60
  text "5" at 13184.2,5627.26 h60
  text "3" at 14017.2,5627.26 h60
  text "MIL" at 14133.46,5627.26 h60
  text "HOLE SIZE TOLERANCE (UNLESS OTHERWISE SPECIFIED):" at 11408.23,5528.95 h60
  text "+/-" at 13778,5526.07 h60
  text "3" at 14017.2,5525.01 h60
  text "MIL" at 14133.46,5525.01 h60
  text "MATERIAL:" at 11333.46,5387.36 h60
  text "FR-4 High Tg" at 12319.9,5258.84 h60
  text "X" at 12175.46,5250.85 h60
  text "FR-408" at 11754.46,5246.33 h60
  text "OTHER" at 13242.46,5246.33 h60
  text "62 MIL (1.6mm) +/-10%" at 12074.56,5103.3 h60
  text "X" at 11954.46,5100.85 h60
  text "THICKNESS:" at 11408.23,5095.08 h60
  text "OTHER" at 13359.46,5095.08 h60
  text "TOLERANCE:" at 11408.23,4956.76 h60
  text "X" at 12256.46,4956.76 h60
  text "ANSI IPC-6012 TYPE 3 CLASS 2" at 12434.48,4956.76 h60
  text "OTHER +/-" at 12434.46,4812.58 h60
  text "BOW & TWIST:" at 11408.23,4667.39 h60
  text "X" at 12256.46,4667.39 h60
  text "ANSI IPC-6012 TYPE 3 CLASS 2" at 12434.48,4667.39 h60
  text "OTHER +/-" at 12434.46,4520.69 h60
  text "DRILLING:" at 11333.46,4390.07 h60
  text "NC_DRILL FILES" at 13094.46,4284.88 h60
  text "REFERENCE:" at 11408.23,4280.95 h60
  text "X" at 12065.46,4280.85 h60
  text "AS SHOWN" at 12243.46,4280.95 h60
  text "X" at 12966.46,4280.95 h60
  text "OTHER" at 13392.46,4138.69 h60
  text "PTH COPPER THICKNESS:" at 11407.91,4135.17 h60
  text "X" at 12547.14,4135.17 h60
  text "20-30 um" at 12675.14,4135.17 h60
  text "BOARD FINISH:" at 11333.46,3987.57 h60
  text "SILKSCREEN:" at 11488.68,3877.44 h60
  text "X" at 12446.46,3877.44 h60
  text "TOP" at 12563.46,3877.44 h60
  text "X" at 12956.46,3877.44 h60
  text "BOTTOM" at 13074.46,3877.44 h60
  text "SILKSCREEN COLOR:" at 11488.68,3722.25 h60
  text "X" at 12445.46,3722.25 h60
  text "WHITE" at 12563.46,3722.25 h60
  text "OTHER" at 13074.46,3722.25 h60
  text "X" at 12576.46,3578.8 h60
  text "GREEN" at 12694.46,3578.8 h60
  text "OTHER" at 13312.46,3578.8 h60
  text "SOLDER RESIST COLOR:" at 11488.68,3571.94 h60
  text "X" at 12576.46,3424.55 h60
  text "MATTE" at 12694.46,3424.55 h60
  text "SEMI-GLOSS" at 13312,3423.91 h60
  text "IMMERSION GOLD (ENIG)" at 12394.46,3251.78 h60
  text "ENEPIG" at 13732,3244.56 h60
  text "SURFACE FINISH:" at 11333.46,3243.56 h60
  text "X" at 12216.46,3243.56 h60
  text "IMM. TIN/SILVER OR EQUIV" at 11663,3106.24 h60
  text "OTHER" at 13094.46,3102.31 h60
  text "ARRAY/PANEL:" at 11333.46,2946.93 h60
  text "CUT AND TRIM PER M1 BOARD OUTLINE" at 12394.46,2938.71 h60
  text "N.C. ROUTE" at 12394.46,2802.74 h60
  text "X" at 13082.46,2802.74 h60
  text "V. SCORE" at 13260.46,2802.74 h60
  text "CERTIFICATION:" at 11333.46,2673.61 h60
  text "MATERIALS AND WORKMANSHIP FOR ALL PCBS" at 12058.46,2673.61 h60
  text "TO MEET OR EXCEED THE REQUIREMENTS OF:" at 12058.46,2579.55 h60
  text "X" at 11695.97,2450.92 h60
  text "ANSI IPC-A-600F CLASS ->" at 11823.96,2450.92 h60
  text "X" at 13471.97,2450.92 h60
  text "2" at 13581.96,2450.92 h60
  text "1" at 13266.96,2449.43 h60
  text "3" at 13935.96,2449.43 h60
  text "X" at 12507.97,2303.24 h60
  text "RoHS" at 12635.96,2303.24 h60
  text "OTHER" at 13280.36,2303.24 h60
  text "PER ORDER" at 13677.42,2303.24 h60
  text "ALL BOARDS MUST MEET OR EXCEED UL94-V0 REQUIREMENTS." at 11361,2149.41 h60
  text "PCB MUST BEAR THE UL94V-0 UL REGISTERED MATERIAL ID NUMBER" at 11361,2033.35 h60
  text "ADDITIONAL REQUIREMENTS:" at 11333.46,1863.92 h60
  text "MICROSECTION:" at 11408.23,1756.8 h60
  text "YES" at 12313.96,1756.8 h60
  text "REQUIRED" at 13175.46,1612.46 h60
  text "BARE BOARD ELEC. TEST:" at 11408.23,1609.61 h60
  text "NONE" at 12713.96,1609.61 h60
  text "X" at 13057.46,1609.61 h60
  text "PER ORDER" at 13767.46,1609.61 h60
  text "XX MIL VIAS REQUIRE NON-CONDUCTIVE FILL AND PLANARIZE" at 11576.38,1404.66 h59
  text "XX MIL VIAS REQUIRE CONDUCTIVE FILL AND PLANARIZE" at 11584.38,1300.69 h60
  text "OUTER XX MIL TRACES REQUIRE 50 OHM SINGLE-ENDED IMPEDANCE" at 11583.39,1137.3 h58
  text "LAYER 2 & 3 (INNER LAYERS) XX MIL WIDE, XX MIL SPACE / TRACES REQUIRE 100 OHM DIFFERENTIAL IMPEDANCE" at 11575.39,901.59 h60
  text ".Layer_Name" at 577,-848.65 h60
M11 Gerber Information:
  lines w10: -292,-920.32 6308,-920.32 ; -292,-716.99 6310,-716.99 ; -292,-513.66 -292,-1123.66 3713,-1123.66 6310,-1123.66 6310,-513.66 -291.5,-513.66 -291.5,-1123.66 1284,-1123.66 ; 2173,-1123.66 2173,-513.66 ; 3440,-716.99 3440,-513.66 ; 4280,-716.99 4280,-513.66 ; 4902,-1130.16 4902,-927.32
  text "ALL ARTWORK VIEWED FROM TOP SIDE" at -228.5,-645.82 h60
  text "BOARD #:" at 2248,-645.82 h60
  text ".PRJ_Number" at 2793.5,-645.82 h60
  text "REV:" at 3638,-645.82 h60
  text ".PCB_Rev" at 3929.5,-645.82 h60
  text "SVN REV:" at 4476,-645.82 h60
  text ".VersionControl_RevNumber" at 4982,-645.82 h60
  text "LAYER NAME =" at -228.5,-848.65 h60
  text "TID #:" at 2248,-849.16 h60
  text ".TID" at 2793.5,-849.16 h60
  text "PLOT NAME =" at -228.5,-1054.49 h60
  text ".plot_File_Name" at 577,-1054.49 h60
  text "GENERATED    :" at 2250,-1054.49 h60
  text ".Print_Date" at 3119.5,-1054.49 h60
  text ".Print_Time" at 3848.5,-1054.49 h60
  text "TEXAS INSTRUMENTS" at 5113,-1054.49 h60
M12 Stackup:
  drawing of 191 lines, arcs and shapes, not listed
  text "Layer" at 9821.59,7884.78 h60
  text "Name" at 10231.51,7884.78 h60
  text "Material" at 11161.25,7884.78 h60
  text "Thickness" at 12021.02,7884.78 h60
  text "Constant" at 12670.85,7884.78 h60
  text "Board Layer Stack" at 13240.71,7884.78 h60
  text "Top Overlay" at 10231.51,7764.78 h60
  text "Top Solder" at 10231.51,7644.78 h60
  text "Solder Resist" at 11161.25,7644.78 h60
  text "0.40mil" at 12021.02,7644.78 h60
  text "3.5" at 12670.85,7644.78 h60
  text "1" at 9821.59,7524.78 h60
  text "Top Layer" at 10231.51,7524.78 h60
  text "1.40mil" at 12021.02,7524.78 h60
  text "Dielectric1" at 10231.51,7404.78 h60
  text "FR-4 High Tg" at 11161.25,7404.78 h60
  text "59.20mil" at 12021.02,7404.78 h60
  text "4" at 12670.85,7404.78 h60
  text "2" at 9821.59,7284.78 h60
  text "Bottom Layer" at 10231.51,7284.78 h60
  text "1.40mil" at 12021.02,7284.78 h60
  text "Bottom Solder" at 10231.51,7164.78 h60
  text "Solder Resist" at 11161.25,7164.78 h60
  text "0.40mil" at 12021.02,7164.78 h60
  text "3.5" at 12670.85,7164.78 h60
  text "Bottom Overlay" at 10231.51,7044.78 h60
  text ".Layer_Name" at 577,-848.65 h60
M13 Component Bodies Top:
  text ".Layer_Name" at 577,-848.65 h60
M14 Component Bodies Bottom:
  text ".Layer_Name" at 577,-848.65 h60
M15 Courtyards Top:
  text ".Layer_Name" at 577,-848.65 h60
M16 Courtyards Bottom:
  text ".Layer_Name" at 577,-848.65 h60
Drill Drawing:
  drawing of 184 lines, arcs and shapes, not listed
  text "Symbol" at 7106.99,6782.62 h72
  text "Quantity" at 7407.55,6782.62 h72
  text "Finished Hole Size" at 7739.55,6782.62 h72
  text "Plated" at 8376.12,6782.62 h72
  text "Hole Type" at 8635.26,6782.62 h72
  text "Drill Layer Pair" at 9010.42,6782.62 h72
  text "Hole Tolerance" at 9734.75,6782.62 h72
  text "6" at 7407.55,6658.3 h60
  text "137.79mil (3.500mm)" at 7739.55,6658.3 h60
  text "NPTH" at 8376.12,6658.3 h60
  text "Round" at 8635.26,6658.3 h60
  text "Top Layer - Bottom Layer" at 9010.42,6658.3 h60
  text "4" at 7407.55,6533.98 h60
  text "196.85mil (5.000mm)" at 7739.55,6533.98 h60
  text "NPTH" at 8376.12,6533.98 h60
  text "Round" at 8635.26,6533.98 h60
  text "Top Layer - Bottom Layer" at 9010.42,6533.98 h60
  text "B" at 7081.7,6523.99 h55.25
  text "9" at 7407.55,6409.66 h60
  text "11.81mil (0.300mm)" at 7739.55,6409.66 h60
  text "PTH" at 8376.12,6409.66 h60
  text "Round" at 8635.26,6409.66 h60
  text "Top Layer - Bottom Layer" at 9010.42,6409.66 h60
  text "138" at 7407.55,6285.34 h60
  text "16.00mil (0.406mm)" at 7739.55,6285.34 h60
  text "PTH" at 8376.12,6285.34 h60
  text "Round" at 8635.26,6285.34 h60
  text "Top Layer - Bottom Layer" at 9010.42,6285.34 h60
  text "A" at 7081.7,6275.35 h55.25
  text "4" at 7407.55,6161.02 h60
  text "25.59mil (0.650mm)" at 7739.55,6161.02 h60
  text "PTH" at 8376.12,6161.02 h60
  text "Round" at 8635.26,6161.02 h60
  text "Top Layer - Bottom Layer" at 9010.42,6161.02 h60
  text "C" at 7081.7,6151.03 h55.25
  text "12" at 7407.55,6036.7 h60
  text "27.56mil (0.700mm)" at 7739.55,6036.7 h60
  text "PTH" at 8376.12,6036.7 h60
  text "Round" at 8635.26,6036.7 h60
  text "Top Layer - Bottom Layer" at 9010.42,6036.7 h60
  text "8" at 7407.55,5912.38 h60
  text "33.47mil (0.850mm)" at 7739.55,5912.38 h60
  text "PTH" at 8376.12,5912.38 h60
  text "Round" at 8635.26,5912.38 h60
  text "Top Layer - Bottom Layer" at 9010.42,5912.38 h60
  text "56" at 7407.55,5788.06 h60
  text "35.43mil (0.900mm)" at 7739.55,5788.06 h60
  text "PTH" at 8376.12,5788.06 h60
  text "Round" at 8635.26,5788.06 h60
  text "Top Layer - Bottom Layer" at 9010.42,5788.06 h60
  text "4" at 7407.55,5663.74 h60
  text "39.37mil (1.000mm)" at 7739.55,5663.74 h60
  text "PTH" at 8376.12,5663.74 h60
  text "Round" at 8635.26,5663.74 h60
  text "Top Layer - Bottom Layer" at 9010.42,5663.74 h60
  text "+/-3.94mil" at 9734.75,5663.74 h60
  text "12" at 7407.55,5539.42 h60
  text "40.00mil (1.016mm)" at 7739.55,5539.42 h60
  text "PTH" at 8376.12,5539.42 h60
  text "Round" at 8635.26,5539.42 h60
  text "Top Layer - Bottom Layer" at 9010.42,5539.42 h60
  text "9" at 7407.55,5415.1 h60
  text "41.00mil (1.041mm)" at 7739.55,5415.1 h60
  text "PTH" at 8376.12,5415.1 h60
  text "Round" at 8635.26,5415.1 h60
  text "Top Layer - Bottom Layer" at 9010.42,5415.1 h60
  text "+/-5.00mil" at 9734.75,5415.1 h60
  text "14" at 7407.55,5290.78 h60
  text "43.31mil (1.100mm)" at 7739.55,5290.78 h60
  text "PTH" at 8376.12,5290.78 h60
  text "Round" at 8635.26,5290.78 h60
  text "Top Layer - Bottom Layer" at 9010.42,5290.78 h60
  text "+/-1.97mil" at 9734.75,5290.78 h60
  text "4" at 7407.55,5166.46 h60
  text "43.31mil (1.100mm)" at 7739.55,5166.46 h60
  text "PTH" at 8376.12,5166.46 h60
  text "Round" at 8635.26,5166.46 h60
  text "Top Layer - Bottom Layer" at 9010.42,5166.46 h60
  text "10" at 7407.55,5042.14 h60
  text "45.28mil (1.150mm)" at 7739.55,5042.14 h60
  text "PTH" at 8376.12,5042.14 h60
  text "Round" at 8635.26,5042.14 h60
  text "Top Layer - Bottom Layer" at 9010.42,5042.14 h60
  text "18" at 7407.55,4917.82 h60
  text "49.21mil (1.250mm)" at 7739.55,4917.82 h60
  text "PTH" at 8376.12,4917.82 h60
  text "Round" at 8635.26,4917.82 h60
  text "Top Layer - Bottom Layer" at 9010.42,4917.82 h60
  text "10" at 7407.55,4793.5 h60
  text "51.18mil (1.300mm)" at 7739.55,4793.5 h60
  text "PTH" at 8376.12,4793.5 h60
  text "Round" at 8635.26,4793.5 h60
  text "Top Layer - Bottom Layer" at 9010.42,4793.5 h60
  text "4" at 7407.55,4669.18 h60
  text "55.12mil (1.400mm)" at 7739.55,4669.18 h60
  text "PTH" at 8376.12,4669.18 h60
  text "Round" at 8635.26,4669.18 h60
  text "Top Layer - Bottom Layer" at 9010.42,4669.18 h60
  text "2" at 7407.55,4544.86 h60
  text "121.00mil (3.073mm)" at 7739.55,4544.86 h60
  text "PTH" at 8376.12,4544.86 h60
  text "Round" at 8635.26,4544.86 h60
  text "Top Layer - Bottom Layer" at 9010.42,4544.86 h60
  text "+/-2.00mil" at 9734.75,4544.86 h60
  text "324 Total" at 7407.55,4420.54 h60
  text ".Layer_Name" at 577,-848.65 h60
M17 Embedded Cavity:
  text ".Layer_Name" at 577,-848.65 h60
M18 Embedded Assembly:
  text ".Layer_Name" at 577,-848.65 h60
M19 Embedded Keepout:
  text ".Layer_Name" at 577,-848.65 h60

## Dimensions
0,-390.16 to 1000,-390.16 on M2 Board Dimensions
0,9.84 to 6131.89,600.39 on M2 Board Dimensions
0,9.84 to 5742.63,9.83 on M2 Board Dimensions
